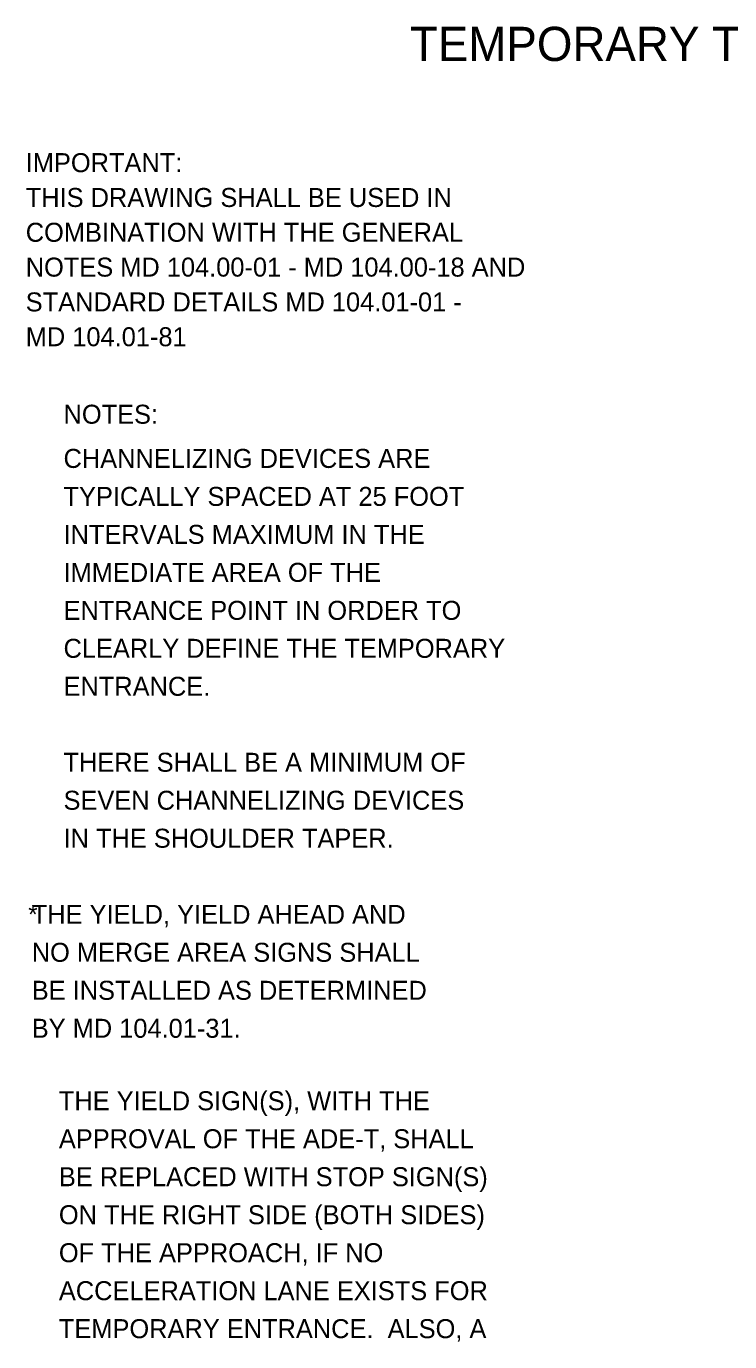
# Model space of a CAD drawing. Extents: x 612.48 to 619.85, y 611.03 to 621.01.
# Drawn here: x 612.803 to 615.025, y 616.854 to 621.01 of the extents above; entities that cross this region are included whole.
import ezdxf

# ---------------------------------------------------------------- set-up
doc = ezdxf.new("R2010")
doc.units = 0
doc.layers.add('DETL-NOTE', color=7, linetype='Continuous')
doc.layers.add('DETL-TITL', color=7, linetype='Continuous')

msp = doc.modelspace()

# ---------------------------------------------------------------- texts
at = {"layer": 'DETL-NOTE'}
for s, height, p in [('IMPORTANT:', 0.06, (612.801, 620.5494)), ('THIS DRAWING SHALL BE USED IN', 0.06, (612.801, 620.4394)), ('COMBINATION WITH THE GENERAL', 0.06, (612.801, 620.3294)), ('NOTES MD 104.00-01 - MD 104.00-18 AND', 0.06, (612.801, 620.2194)), ('STANDARD DETAILS MD 104.01-01 -', 0.06, (612.801, 620.1094)), ('MD 104.01-81', 0.06, (612.801, 619.9994)), ('NOTES:', 0.06, (612.9204, 619.7546)), ('CHANNELIZING DEVICES ARE ', 0.06, (612.9204, 619.615)), ('TYPICALLY SPACED AT 25 FOOT ', 0.06, (612.9204, 619.495)), ('INTERVALS MAXIMUM IN THE ', 0.06, (612.9204, 619.375)), ('IMMEDIATE AREA OF THE ', 0.06, (612.9204, 619.255)), ('ENTRANCE POINT IN ORDER TO ', 0.06, (612.9204, 619.135)), ('CLEARLY DEFINE THE TEMPORARY ', 0.06, (612.9204, 619.015)), ('ENTRANCE.', 0.06, (612.9204, 618.895)), ('THERE SHALL BE A MINIMUM OF ', 0.06, (612.9204, 618.655)), ('SEVEN CHANNELIZING DEVICES ', 0.06, (612.9204, 618.535)), ('IN THE SHOULDER TAPER.', 0.06, (612.9204, 618.415)), ('*', 0.057, (612.8088, 618.1762)), ('  THE YIELD, YIELD AHEAD AND ', 0.06, (612.7754, 618.1746)), ('  NO MERGE AREA SIGNS SHALL', 0.06, (612.7754, 618.0546)), ('  BE INSTALLED AS DETERMINED', 0.06, (612.7754, 617.9346)), ('  BY MD 104.01-31.', 0.06, (612.7754, 617.8146)), ('THE YIELD SIGN(S), WITH THE ', 0.06, (612.9057, 617.5856)), ('APPROVAL OF THE ADE-T, SHALL', 0.06, (612.9057, 617.4656)), ('BE REPLACED WITH STOP SIGN(S)', 0.06, (612.9057, 617.3456)), ('ON THE RIGHT SIDE (BOTH SIDES)', 0.06, (612.9057, 617.2256)), ('OF THE APPROACH, IF NO', 0.06, (612.9057, 617.1056)), ('ACCELERATION LANE EXISTS FOR', 0.06, (612.9057, 616.9856)), ('TEMPORARY ENTRANCE.  ALSO, A', 0.06, (612.9057, 616.8656))]:
    msp.add_text(s, height=height, dxfattribs=at).set_placement(p)
at = {"layer": 'DETL-TITL'}
msp.add_text('TEMPORARY TRAFFIC CONTROL TYPICAL APPLICATION', height=0.108, dxfattribs=at).set_placement((614.0149, 620.9006))

doc.saveas('drawing.dxf')
